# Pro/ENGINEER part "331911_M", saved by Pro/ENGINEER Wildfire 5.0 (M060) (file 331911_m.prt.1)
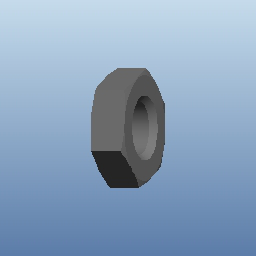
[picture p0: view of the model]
Units: PSOLunit; MM, KILOGRAM, SECS

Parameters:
  NN = "602105-M, 606104-M, 624105-M"
  NT = "Metric Nut"
  NB = "331911-M"
  NBSYN = "$PN."
  LINA = "331911-M"
  PN = "331911-M"
  ARTICLENO = "331911-M"
  BOMINFO = "331911-M"
  CREATOR = "CADENAS GmbH"
  PLACEMENT = "B"
  METRIC = "YES"

Other parameters: H, W, NUTSIZE, WEIGHT, THREADS_PER_INCH, SURF_AREA, MASS

Other named items: COORD, DEF-PLANE-AXIS, DEF-PLANE-AXIS-INV, CS1, CS2, NUT1_CSYS, NUT2_CSYS, CONN, MASS, RIGHT, TOP, FRONT, NUT1_XPLN, NUT1_YPLN, NUT1_ZPLN, NUT2_XPLN, NUT2_YPLN, NUT2_ZPLN, NUT1_ZAXS, NUT2_ZAXS

Named dimensions: THLEN, THDIA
